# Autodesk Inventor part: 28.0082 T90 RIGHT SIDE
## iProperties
Created: 2007-04
Part Number: 28.0082 T90 RIGHT SIDE
Document SubType Name: Modeling
Designer: Andy Moles
Material: Aluminum-6061
Mass: 895.865 g
Surface Area: 541.018 cm^2
Volume: 330.577 cm^3
Density: 2.71 g/cm^3
Author: Andy Moles
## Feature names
1. Extrusion1
2. Chamfer1
3. Hole1
4. Hole2
5. Hole3
6. Hole4
7. Hole5
8. Extrusion2
9. Extrusion3
10. Hole6
11. Extrusion4
12. Hole7
13. Hole8
14. Hole9
15. Hole10
